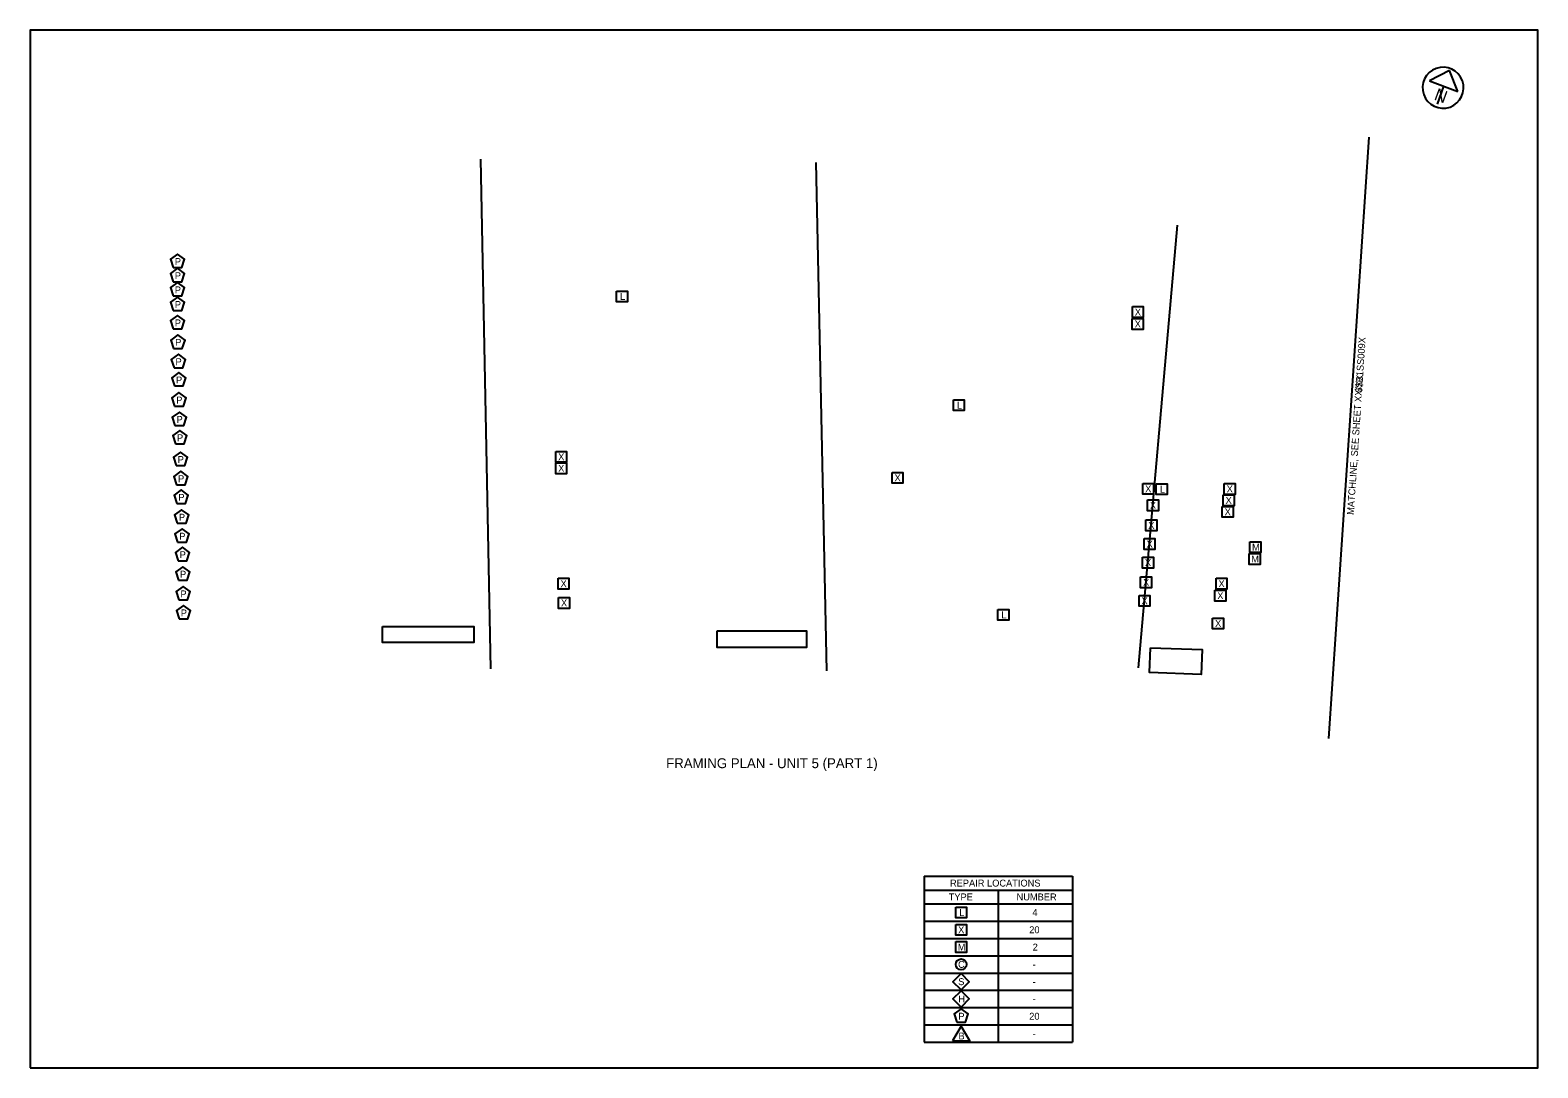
# Model space of a CAD drawing. Extents: x 100 to 130.5, y 100 to 121.
import ezdxf

# ---------------------------------------------------------------- set-up
doc = ezdxf.new("R2010")
doc.units = 0
for name, color, linetype in [('BR_P_Gen_Text', 7, 'Continuous'), ('BR_X_Sub_Centerline', 7, 'Continuous'), ('BR_X_Sub_Text', 7, 'Continuous'), ('SC_Scratch1', 7, 'Continuous'), ('SH_Data', 7, 'Continuous')]:
    doc.layers.add(name, color=color, linetype=linetype)

msp = doc.modelspace()

# ---------------------------------------------------------------- linework, layer by layer
at = {"layer": 'BR_P_Gen_Text'}
for p, q in [((127.078, 118.835), (126.265, 106.665)), ((118.083, 103.879), (118.083, 100.519)), ((118.083, 103.879), (121.083, 103.879)), ((121.083, 103.879), (121.083, 100.519)), ((118.083, 103.599), (121.083, 103.599)), ((119.583, 103.599), (119.583, 100.519)), ((118.083, 103.319), (121.083, 103.319)), ((118.083, 102.969), (121.083, 102.969)), ((118.083, 102.619), (121.083, 102.619)), ((118.083, 102.269), (121.083, 102.269)), ((118.083, 101.919), (121.083, 101.919)), ((118.083, 101.569), (121.083, 101.569)), ((118.083, 101.219), (121.083, 101.219)), ((118.083, 100.869), (121.083, 100.869)), ((118.083, 100.519), (121.083, 100.519))]:
    msp.add_line(p, q, dxfattribs=at)
for points in [[(102.895, 116.195), (103.071, 116.195), (103.125, 116.363), (102.983, 116.467), (102.84, 116.363)], [(102.895, 115.909), (103.071, 115.909), (103.125, 116.077), (102.983, 116.181), (102.84, 116.077)], [(102.895, 115.621), (103.071, 115.621), (103.125, 115.789), (102.983, 115.893), (102.84, 115.789)], [(102.895, 115.325), (103.071, 115.325), (103.125, 115.493), (102.983, 115.597), (102.84, 115.493)], [(111.861, 115.721), (112.081, 115.721), (112.081, 115.501), (111.861, 115.501)], [(122.297, 115.405), (122.517, 115.405), (122.517, 115.185), (122.297, 115.185)], [(102.895, 114.954), (103.071, 114.954), (103.125, 115.122), (102.983, 115.225), (102.84, 115.122)], [(122.295, 115.165), (122.515, 115.165), (122.515, 114.945), (122.295, 114.945)], [(102.902, 114.56), (103.078, 114.56), (103.133, 114.728), (102.99, 114.832), (102.848, 114.728)], [(102.91, 114.169), (103.086, 114.169), (103.14, 114.337), (102.998, 114.44), (102.855, 114.337)], [(102.919, 113.799), (103.095, 113.799), (103.15, 113.966), (103.007, 114.07), (102.864, 113.966)], [(102.923, 113.393), (103.099, 113.393), (103.153, 113.561), (103.011, 113.664), (102.868, 113.561)], [(118.676, 113.52), (118.896, 113.52), (118.896, 113.3), (118.676, 113.3)], [(102.93, 112.999), (103.106, 112.999), (103.16, 113.167), (103.018, 113.271), (102.875, 113.167)], [(102.939, 112.629), (103.115, 112.629), (103.17, 112.797), (103.027, 112.9), (102.884, 112.797)], [(102.953, 112.188), (103.129, 112.188), (103.184, 112.356), (103.041, 112.46), (102.898, 112.356)], [(110.632, 112.476), (110.852, 112.476), (110.852, 112.256), (110.632, 112.256)], [(110.632, 112.243), (110.852, 112.243), (110.852, 112.023), (110.632, 112.023)], [(102.96, 111.801), (103.136, 111.801), (103.191, 111.968), (103.048, 112.072), (102.905, 111.968)], [(117.437, 112.051), (117.657, 112.051), (117.657, 111.831), (117.437, 111.831)], [(102.967, 111.424), (103.143, 111.424), (103.198, 111.592), (103.055, 111.696), (102.912, 111.592)], [(122.507, 111.828), (122.727, 111.828), (122.727, 111.608), (122.507, 111.608)], [(122.782, 111.821), (123.002, 111.821), (123.002, 111.601), (122.782, 111.601)], [(124.156, 111.826), (124.376, 111.826), (124.376, 111.606), (124.156, 111.606)], [(122.603, 111.494), (122.823, 111.494), (122.823, 111.274), (122.603, 111.274)], [(124.115, 111.363), (124.335, 111.363), (124.335, 111.143), (124.115, 111.143)], [(124.134, 111.594), (124.354, 111.594), (124.354, 111.374), (124.134, 111.374)], [(102.977, 111.022), (103.153, 111.022), (103.208, 111.189), (103.065, 111.293), (102.922, 111.189)], [(122.57, 111.088), (122.79, 111.088), (122.79, 110.868), (122.57, 110.868)], [(102.984, 110.637), (103.16, 110.637), (103.215, 110.804), (103.072, 110.908), (102.93, 110.804)], [(102.992, 110.263), (103.168, 110.263), (103.222, 110.431), (103.08, 110.535), (102.937, 110.431)], [(122.535, 110.71), (122.755, 110.71), (122.755, 110.49), (122.535, 110.49)], [(124.676, 110.647), (124.896, 110.647), (124.896, 110.427), (124.676, 110.427)], [(102.999, 109.869), (103.175, 109.869), (103.23, 110.037), (103.087, 110.14), (102.945, 110.037)], [(122.502, 110.335), (122.722, 110.335), (122.722, 110.115), (122.502, 110.115)], [(124.661, 110.408), (124.881, 110.408), (124.881, 110.188), (124.661, 110.188)], [(110.68, 109.907), (110.9, 109.907), (110.9, 109.687), (110.68, 109.687)], [(122.465, 109.936), (122.685, 109.936), (122.685, 109.716), (122.465, 109.716)], [(123.99, 109.908), (124.21, 109.908), (124.21, 109.688), (123.99, 109.688)], [(103.008, 109.47), (103.184, 109.47), (103.239, 109.638), (103.096, 109.741), (102.954, 109.638)], [(110.688, 109.519), (110.908, 109.519), (110.908, 109.299), (110.688, 109.299)], [(122.432, 109.561), (122.652, 109.561), (122.652, 109.341), (122.432, 109.341)], [(123.966, 109.665), (124.186, 109.665), (124.186, 109.445), (123.966, 109.445)], [(103.015, 109.085), (103.192, 109.085), (103.246, 109.253), (103.103, 109.356), (102.961, 109.253)], [(119.575, 109.277), (119.795, 109.277), (119.795, 109.057), (119.575, 109.057)], [(123.921, 109.103), (124.141, 109.103), (124.141, 108.883), (123.921, 108.883)], [(118.723, 103.254), (118.943, 103.254), (118.943, 103.034), (118.723, 103.034)], [(118.723, 102.904), (118.943, 102.904), (118.943, 102.684), (118.723, 102.684)], [(118.723, 102.554), (118.943, 102.554), (118.943, 102.334), (118.723, 102.334)], [(118.833, 101.909), (118.998, 101.744), (118.833, 101.579), (118.668, 101.744)], [(118.833, 101.559), (118.998, 101.394), (118.833, 101.229), (118.668, 101.394)], [(118.745, 100.923), (118.922, 100.923), (118.976, 101.091), (118.833, 101.194), (118.691, 101.091)], [(118.66, 100.544), (119.007, 100.544), (118.833, 100.844)]]:
    msp.add_lwpolyline(points, close=True, dxfattribs=at)
msp.add_circle((118.833, 102.094), 0.11, dxfattribs=at)
at = {"layer": 'BR_X_Sub_Centerline'}
for p, q in [((109.317, 108.072), (109.114, 118.387)), ((116.116, 108.037), (115.902, 118.322)), ((122.424, 108.092), (123.211, 117.051))]:
    msp.add_line(p, q, dxfattribs=at)
at = {"layer": 'BR_X_Sub_Text'}
for points in [[(107.129, 108.932), (108.978, 108.932), (108.978, 108.608), (107.129, 108.608)], [(113.896, 108.843), (115.704, 108.843), (115.704, 108.51), (113.896, 108.51)], [(122.662, 108.499), (123.708, 108.463), (123.691, 107.962), (122.644, 107.999)]]:
    msp.add_lwpolyline(points, close=True, dxfattribs=at)
at = {"layer": 'SC_Scratch1'}
msp.add_lwpolyline([(100, 100), (130.5, 100), (130.5, 121), (100, 121)], close=True, dxfattribs=at)
at = {"layer": 'SH_Data'}
for p, q in [((128.711, 120.186), (128.305, 119.971)), ((128.883, 119.76), (128.711, 120.186)), ((128.305, 119.971), (128.883, 119.76)), ((128.594, 119.866), (128.461, 119.502))]:
    msp.add_line(p, q, dxfattribs=at)
msp.add_arc((128.583, 119.835), 0.415, 109.7139, 109.6974, dxfattribs=at)

# ---------------------------------------------------------------- texts
at = {"layer": 'BR_P_Gen_Text'}
for s, height, p in [('P', 0.14, (102.927, 116.247)), ('P', 0.14, (102.927, 115.961)), ('P', 0.14, (102.927, 115.673)), ('L', 0.14, (111.933, 115.541)), ('P', 0.14, (102.927, 115.377)), ('X', 0.14, (122.347, 115.225)), ('P', 0.14, (102.927, 115.005)), ('X', 0.14, (122.345, 114.985)), ('P', 0.14, (102.934, 114.612)), ('P', 0.14, (102.941, 114.22)), ('P', 0.14, (102.951, 113.85)), ('P', 0.14, (102.955, 113.444)), ('L', 0.14, (118.748, 113.34)), ('P', 0.14, (102.962, 113.051)), ('P', 0.14, (102.971, 112.68)), ('P', 0.14, (102.985, 112.24)), ('X', 0.14, (110.682, 112.296)), ('P', 0.14, (102.992, 111.852)), ('X', 0.14, (110.682, 112.063)), ('X', 0.14, (117.486, 111.871)), ('X', 0.14, (122.556, 111.648)), ('L', 0.14, (122.854, 111.641)), ('X', 0.14, (124.205, 111.646)), ('P', 0.14, (102.999, 111.476)), ('X', 0.14, (122.652, 111.314)), ('X', 0.14, (124.183, 111.414)), ('P', 0.14, (103.009, 111.073)), ('X', 0.14, (122.619, 110.908)), ('X', 0.14, (124.164, 111.183)), ('P', 0.14, (103.016, 110.688)), ('P', 0.14, (103.024, 110.315)), ('X', 0.14, (122.584, 110.53)), ('M', 0.14, (124.718, 110.467)), ('X', 0.14, (122.552, 110.155)), ('M', 0.14, (124.703, 110.228)), ('P', 0.14, (103.031, 109.92)), ('X', 0.14, (110.729, 109.727)), ('X', 0.14, (122.514, 109.756)), ('X', 0.14, (124.039, 109.728)), ('P', 0.14, (103.04, 109.521)), ('X', 0.14, (122.482, 109.381)), ('X', 0.14, (124.015, 109.485)), ('P', 0.14, (103.047, 109.136)), ('X', 0.14, (110.738, 109.339)), ('L', 0.14, (119.647, 109.097)), ('X', 0.14, (123.971, 108.923)), ('FRAMING PLAN - UNIT 5 (PART 1)', 0.2, (112.866, 106.065)), ('REPAIR LOCATIONS', 0.14, (118.608, 103.669)), ('TYPE', 0.14, (118.582, 103.389)), ('NUMBER', 0.14, (119.955, 103.389)), ('L', 0.14, (118.795, 103.074)), ('4', 0.14, (120.275, 103.074)), ('X', 0.14, (118.773, 102.724)), ('20', 0.14, (120.211, 102.724)), ('M', 0.14, (118.765, 102.374)), ('2', 0.14, (120.281, 102.374)), ('C', 0.14, (118.771, 102.024)), ('-', 0.14, (120.28, 102.024)), ('S', 0.14, (118.775, 101.674)), ('-', 0.14, (120.28, 101.674)), ('H', 0.14, (118.777, 101.324)), ('-', 0.14, (120.28, 101.324)), ('P', 0.14, (118.777, 100.974)), ('20', 0.14, (120.211, 100.974)), ('B', 0.14, (118.779, 100.574)), ('-', 0.14, (120.28, 100.624))]:
    msp.add_text(s, height=height, dxfattribs=at).set_placement(p)
for s, p in [('$$B1SS009X', (126.943, 113.661)), ('MATCHLINE, SEE SHEET XX/XX', (126.777, 111.187))]:
    msp.add_text(s, height=0.14, rotation=86.1762, dxfattribs=at).set_placement(p)
at = {"layer": 'SH_Data'}
msp.add_text('N', height=0.25, rotation=339.9341, dxfattribs=at).set_placement((128.385, 119.597))

doc.saveas('drawing.dxf')
